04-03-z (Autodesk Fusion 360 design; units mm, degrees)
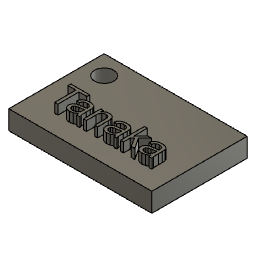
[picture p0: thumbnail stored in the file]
sketch "スケッチ2" plane through (0, 0, 0) normal (0, 1, 0) x axis (1, 0, 0)
  line L1 (-15, 10) -> (15, 10)
  line L2 (-15, -10) -> (-15, 10)
  line L3 (15, -10) -> (-15, -10)
  line L4 (15, 10) -> (15, -10)
  line L5 (-15, -10) -> (15, 10)
  line L6 (15, -10) -> (-15, 10)
  point P6 (0, 0)
  point P1 (0, 0)
  point P2 (15, 10)
  point P3 (-15, 10)
  point P5 (15, -10)
  horizontal L1
  perpendicular L1 L2
  parallel L1 L3
  parallel L2 L4
  coincident L5 P6
  coincident L6 P6
  coincident P1 P6
  dimension "d5" distance P2 P3 = 30
  dimension "d6" distance P2 P5 = 20
extrude "押し出し2" new body sketch "スケッチ2" profile of L1 L2 L3 L4 along normal blind 4
hole "穴" HoleDepth 4 HoleDiameter 4 TipAngle 118 RefDim1 4 RefDim2 4
sketch "スケッチ3" plane through (0, 4, 0) normal (0, 1, 0) x axis (-1, 0, 0)
  dimension "d14" = 5
  dimension "d15" = 4
  dimension "d16" = 11
extrude "押し出し3" add sketch "スケッチ3" along normal blind 2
